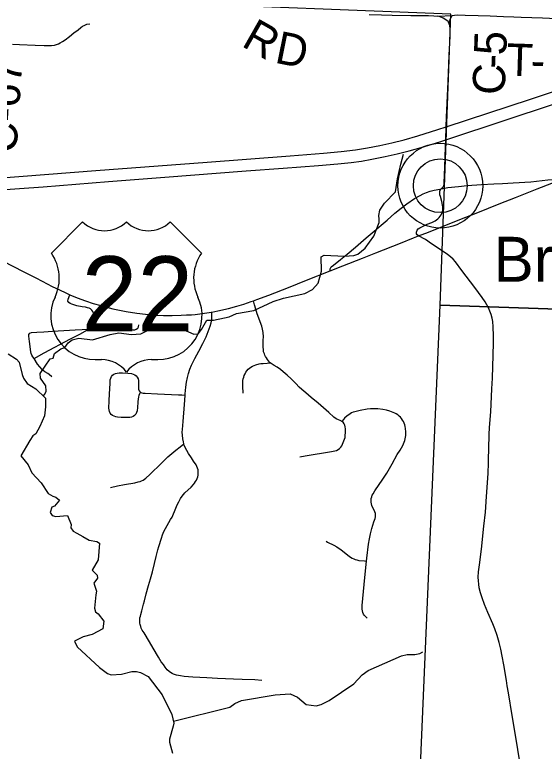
# Model space of a CAD drawing. Extents: x 0 to 34, y 0 to 22.
# Drawn here: x 7.308 to 8.237, y 16.42 to 17.712 of the extents above; entities that cross this region are included whole.
import ezdxf

# ---------------------------------------------------------------- set-up
doc = ezdxf.new("R2010")
doc.units = 0
for name, color, linetype in [('GM_X_County_Road', 7, 'Continuous'), ('GM_X_County_Road_Text', 7, 'Continuous'), ('GM_X_Interstate_Route', 7, 'Continuous'), ('GM_X_Minor_River', 7, 'Continuous'), ('GM_X_Section', 7, 'Continuous'), ('GM_X_Township_Road', 7, 'Continuous'), ('GM_X_Township_Road_Text', 7, 'Continuous'), ('GM_X_Unincorporated', 7, 'Continuous'), ('GM_X_Unincorporated_Location', 7, 'Continuous'), ('GM_X_Unincorporated_Text', 7, 'Continuous'), ('GM_X_US_Location', 7, 'Continuous'), ('GM_X_US_Route', 7, 'Continuous'), ('GM_X_US_Shield', 7, 'Continuous')]:
    doc.layers.add(name, color=color, linetype=linetype)

msp = doc.modelspace()

# ---------------------------------------------------------------- linework, layer by layer
at = {"layer": 'GM_X_County_Road'}
for points in [[(7.9301, 17.7128), (7.9518, 17.7123), (7.9704, 17.7119), (8.0029, 17.7113), (8.0194, 17.711), (8.0344, 17.7108), (8.0433, 17.7107), (8.0499, 17.7101)], [(8.0707, 17.6967), (8.0692, 17.6994), (8.0685, 17.7005), (8.0646, 17.7037), (8.0602, 17.7065), (8.0547, 17.709), (8.0499, 17.7101)], [(8.0562, 17.4067), (8.0602, 17.4101), (8.0613, 17.4124), (8.0615, 17.4152), (8.0616, 17.4213), (8.0621, 17.4275), (8.0623, 17.4338), (8.0627, 17.4429), (8.0632, 17.4646), (8.0644, 17.493), (8.0653, 17.5156), (8.066, 17.5328), (8.0677, 17.5699), (8.0688, 17.5948), (8.0701, 17.6258), (8.0707, 17.6412), (8.0719, 17.6629), (8.0723, 17.6747), (8.0723, 17.681), (8.0722, 17.6876), (8.0718, 17.6935), (8.0707, 17.6967)], [(8.0166, 17.3242), (8.0143, 17.3263), (8.0133, 17.3279), (8.013, 17.3294), (8.013, 17.3308), (8.0137, 17.3326), (8.0145, 17.3343), (8.0163, 17.3366), (8.0187, 17.3385), (8.0222, 17.3402), (8.0259, 17.342), (8.0321, 17.3447), (8.0402, 17.348), (8.0456, 17.3508), (8.0482, 17.3524), (8.0506, 17.3543), (8.0528, 17.3563), (8.0547, 17.3586), (8.0562, 17.3611), (8.0575, 17.3638), (8.0586, 17.3666), (8.0593, 17.3695), (8.0596, 17.3724), (8.0594, 17.3754), (8.059, 17.3784), (8.0577, 17.3844), (8.055, 17.3933), (8.0543, 17.3964), (8.0539, 17.3996), (8.0539, 17.4029), (8.0555, 17.4059), (8.0562, 17.4067)], [(8.196, 16.3904), (8.1856, 16.4548), (8.1809, 16.4823), (8.1744, 16.5221), (8.1724, 16.5344), (8.1709, 16.5436), (8.1661, 16.5711), (8.1635, 16.5864), (8.1609, 16.5986), (8.158, 16.6106), (8.1545, 16.6226), (8.1505, 16.6344), (8.147, 16.6431), (8.1383, 16.663), (8.1323, 16.6773), (8.1281, 16.6889), (8.1254, 16.6977), (8.1232, 16.7067), (8.1223, 16.7128), (8.1217, 16.7189), (8.1216, 16.725), (8.1221, 16.7343), (8.1234, 16.7466), (8.1271, 16.7743), (8.1315, 16.8144), (8.134, 16.8391), (8.1362, 16.867), (8.1388, 16.9072), (8.1395, 16.9258), (8.1403, 16.9568), (8.1406, 16.9692), (8.1408, 16.9753), (8.1415, 16.9877), (8.1433, 17.0155), (8.1456, 17.0558), (8.1463, 17.0744), (8.1478, 17.1147), (8.1485, 17.1365), (8.1485, 17.1489), (8.1477, 17.1645), (8.1468, 17.1738), (8.1458, 17.18), (8.1442, 17.1861), (8.1421, 17.192), (8.1396, 17.1978), (8.1366, 17.2033), (8.1334, 17.2086), (8.1281, 17.2163), (8.1152, 17.2339), (8.0929, 17.2637), (8.0815, 17.2786), (8.0774, 17.2832), (8.0728, 17.2875), (8.0678, 17.2914), (8.0602, 17.2967), (8.0394, 17.3102), (8.0287, 17.3176), (8.0166, 17.3242)]]:
    msp.add_lwpolyline(points, dxfattribs=at)
at = {"layer": 'GM_X_Interstate_Route'}
for points in [[(7.2772, 17.4256), (7.4507, 17.4388), (7.6458, 17.4538), (7.7914, 17.465), (7.8502, 17.4696), (7.8812, 17.4725), (7.9059, 17.4755), (7.9274, 17.4788), (7.9488, 17.4827), (7.9701, 17.4873), (7.9912, 17.4927), (8.0152, 17.4996), (8.0507, 17.5108), (8.0653, 17.5156), (8.213, 17.5644), (8.2553, 17.5781), (8.2721, 17.5836), (8.3164, 17.5982), (8.39, 17.6229), (8.4432, 17.6401), (8.711, 17.7284)], [(7.2745, 17.4042), (7.3581, 17.4105), (7.4727, 17.4194), (7.5717, 17.4272), (7.7142, 17.4382), (7.7792, 17.4432), (7.8412, 17.4478), (7.8752, 17.4508), (7.8986, 17.4531), (7.9165, 17.4556), (7.9349, 17.4589), (7.958, 17.4634), (7.9792, 17.4682), (8.0003, 17.4735), (8.0211, 17.4794), (8.0538, 17.4896), (8.0644, 17.493), (8.0858, 17.4999), (8.1512, 17.5213), (8.2691, 17.5606)]]:
    msp.add_lwpolyline(points, dxfattribs=at)
at = {"layer": 'GM_X_Minor_River'}
for points in [[(7.6764, 17.1802), (7.6846, 17.1821), (7.6971, 17.1882), (7.7277, 17.1934), (7.7617, 17.2088), (7.7795, 17.2149), (7.8169, 17.2228), (7.8305, 17.2301), (7.8407, 17.2415), (7.8462, 17.262), (7.846, 17.2874), (7.8509, 17.2905), (7.8866, 17.2888), (7.9032, 17.2897), (7.9104, 17.2924), (7.9228, 17.3027), (7.9382, 17.324), (7.9479, 17.3476), (7.9479, 17.3533), (7.9471, 17.3601), (7.9489, 17.3696), (7.9568, 17.3814), (7.9763, 17.4017), (7.9796, 17.4241), (7.9859, 17.4499), (7.9903, 17.4674)], [(7.358, 17.0431), (7.3612, 17.0464), (7.3631, 17.0518), (7.363, 17.0609), (7.3535, 17.0745), (7.3527, 17.0824), (7.3704, 17.1087), (7.3753, 17.1095), (7.3779, 17.1179), (7.3888, 17.1259), (7.396, 17.1282), (7.402, 17.1366), (7.4088, 17.1416), (7.4205, 17.1447), (7.4444, 17.1418), (7.4757, 17.1511), (7.4908, 17.1538), (7.5132, 17.1513), (7.5294, 17.1525), (7.5362, 17.1556), (7.5588, 17.1671), (7.5675, 17.1686), (7.5997, 17.1616), (7.6225, 17.1515), (7.63, 17.1523), (7.6357, 17.1599), (7.6451, 17.1763), (7.6568, 17.1763), (7.6764, 17.1802)], [(7.2969, 17.1171), (7.3114, 17.108), (7.3159, 17.1024), (7.3213, 17.0811), (7.3236, 17.0743), (7.3301, 17.0649), (7.3449, 17.0558), (7.362, 17.0392), (7.3621, 17.024), (7.3603, 17.0085), (7.3524, 16.9898), (7.3449, 16.9769), (7.34, 16.9734), (7.3348, 16.9651), (7.3186, 16.938), (7.3316, 16.9221), (7.3381, 16.9081), (7.3548, 16.8908), (7.367, 16.8722), (7.375, 16.8673), (7.3803, 16.8658), (7.3867, 16.8602), (7.3781, 16.8499), (7.3732, 16.8483), (7.3702, 16.8385), (7.3736, 16.8335), (7.3801, 16.8317), (7.4005, 16.8337), (7.407, 16.8174), (7.4063, 16.8117), (7.4105, 16.8057), (7.4173, 16.8023), (7.4275, 16.7966), (7.4385, 16.7902), (7.4522, 16.788), (7.4571, 16.7846), (7.4546, 16.7554), (7.4441, 16.7375), (7.4525, 16.7288), (7.4536, 16.7235), (7.4469, 16.7144), (7.4515, 16.7003), (7.4507, 16.6939), (7.4482, 16.6707), (7.4498, 16.6646), (7.4547, 16.6609), (7.4642, 16.648), (7.4628, 16.6343), (7.4443, 16.6248), (7.428, 16.6205), (7.4133, 16.6128), (7.4175, 16.603), (7.4567, 16.5667), (7.4707, 16.5562), (7.4775, 16.5536), (7.4953, 16.5548), (7.5135, 16.5598), (7.5218, 16.5595), (7.5286, 16.558), (7.5422, 16.5509), (7.5666, 16.5187), (7.5838, 16.4843), (7.5873, 16.4691), (7.5862, 16.4634), (7.5795, 16.441), (7.5795, 16.4353), (7.5849, 16.4163)], [(7.5865, 16.4724), (7.6858, 16.497), (7.6941, 16.5035), (7.7062, 16.5085), (7.7652, 16.5188), (7.7913, 16.5201), (7.8046, 16.5148), (7.8195, 16.5017), (7.8373, 16.4991), (7.846, 16.5014), (7.8599, 16.5087), (7.9029, 16.5378), (7.9176, 16.5539), (7.9285, 16.5611), (7.9871, 16.5869), (7.9965, 16.5893), (8.0102, 16.5893), (8.0192, 16.5909), (8.0245, 16.594)]]:
    msp.add_lwpolyline(points, dxfattribs=at)
at = {"layer": 'GM_X_Section'}
for points in [[(7.5782, 18.246), (8.5787, 18.2117), (8.5361, 17.186), (8.0548, 17.2024), (8.0736, 17.7137), (7.5651, 17.7332)], [(8.0548, 17.2024), (8.5361, 17.186), (8.4938, 16.1751), (8.0113, 16.1881)]]:
    msp.add_lwpolyline(points, close=True, dxfattribs=at)
at = {"layer": 'GM_X_Township_Road'}
msp.add_line((8.0499, 17.7101), (8.0762, 17.7113), dxfattribs=at)
for points in [[(8.0707, 17.6967), (8.0711, 17.7001), (8.0715, 17.7019), (8.072, 17.704), (8.0726, 17.7058), (8.0734, 17.7072), (8.0752, 17.7098), (8.0762, 17.7113)], [(8.0762, 17.7113), (8.0799, 17.7118), (8.0848, 17.712), (8.0988, 17.7118), (8.1212, 17.7112), (8.1425, 17.7105), (8.1658, 17.7095), (8.1841, 17.7087), (8.1969, 17.708), (8.2154, 17.7073), (8.234, 17.7067), (8.2463, 17.7063), (8.2658, 17.7057), (8.2864, 17.7047), (8.3106, 17.7036), (8.3324, 17.7021), (8.3538, 17.7008), (8.3699, 17.7001), (8.3856, 17.6998), (8.4067, 17.6991), (8.4217, 17.6989)], [(7.3045, 17.6606), (7.3167, 17.6603), (7.3441, 17.6589), (7.3596, 17.6582), (7.3658, 17.6582), (7.3726, 17.6584), (7.3782, 17.659), (7.3814, 17.6599), (7.3849, 17.6612), (7.3878, 17.6628), (7.3918, 17.6652), (7.3966, 17.6685), (7.4045, 17.6744), (7.4119, 17.6804), (7.4192, 17.6862), (7.4242, 17.6902), (7.4269, 17.6921), (7.4298, 17.6937), (7.4325, 17.6949), (7.4348, 17.6957), (7.4401, 17.6964)], [(8.0562, 17.4067), (8.0682, 17.4089), (8.0866, 17.4112), (8.1023, 17.4127), (8.1271, 17.4142), (8.1488, 17.4153), (8.1643, 17.4161), (8.183, 17.4172), (8.2136, 17.4193), (8.2437, 17.4225), (8.2517, 17.4232), (8.2562, 17.4221), (8.26, 17.4199)], [(7.8617, 17.2629), (7.8618, 17.2661), (7.8622, 17.2678), (7.8628, 17.2689), (7.8634, 17.2697), (7.8673, 17.273), (7.8796, 17.2825), (7.8917, 17.2923), (7.9058, 17.3046), (7.9246, 17.3207), (7.9388, 17.3326), (7.9511, 17.343), (7.9615, 17.352), (7.975, 17.3639), (7.9861, 17.373), (7.996, 17.3803), (8.0099, 17.3898), (8.0195, 17.3954), (8.0248, 17.398), (8.0306, 17.4006), (8.0372, 17.4028), (8.044, 17.4043), (8.0541, 17.4064), (8.0551, 17.4065), (8.0562, 17.4067)], [(7.4423, 17.1623), (7.4446, 17.1732), (7.4461, 17.1792), (7.4466, 17.1822), (7.4468, 17.1853), (7.4464, 17.1884), (7.4454, 17.1913), (7.4437, 17.1939), (7.4413, 17.1959), (7.4386, 17.1973), (7.4356, 17.1982), (7.4326, 17.1989), (7.4265, 17.1999), (7.4173, 17.2014), (7.4083, 17.2042), (7.4054, 17.2053), (7.403, 17.2071), (7.4016, 17.2098), (7.4018, 17.2129), (7.405, 17.221)], [(7.7565, 17.1015), (7.7554, 17.1023), (7.7532, 17.1047), (7.7514, 17.1073), (7.7499, 17.1099), (7.7484, 17.1124), (7.7471, 17.115), (7.7462, 17.1172), (7.7449, 17.1207), (7.7444, 17.124), (7.744, 17.1294), (7.7442, 17.1413), (7.7444, 17.1472), (7.7438, 17.1548), (7.7429, 17.1604), (7.7416, 17.1659), (7.739, 17.1732), (7.7365, 17.1796), (7.7335, 17.1875), (7.7311, 17.1956), (7.7291, 17.2034), (7.7273, 17.2103)], [(7.6072, 17.0449), (7.6074, 17.0469), (7.6085, 17.0586), (7.6096, 17.0675), (7.6113, 17.0758), (7.6129, 17.0828), (7.6155, 17.0903), (7.6186, 17.0973), (7.6242, 17.1089), (7.6312, 17.1216), (7.6382, 17.1356), (7.6439, 17.1468), (7.6477, 17.1562), (7.6511, 17.1659), (7.653, 17.1717), (7.6537, 17.1746), (7.6539, 17.177), (7.6542, 17.1806), (7.654, 17.1861), (7.6539, 17.1904)], [(7.342, 17.109), (7.3399, 17.1122), (7.3384, 17.1149), (7.3372, 17.1177), (7.3363, 17.1207), (7.3338, 17.139), (7.3328, 17.1482), (7.3328, 17.1513), (7.3345, 17.1536), (7.3375, 17.1545), (7.3467, 17.1554), (7.359, 17.156), (7.3743, 17.157), (7.4144, 17.1591), (7.4386, 17.1606)], [(7.342, 17.109), (7.3595, 17.119), (7.406, 17.1434), (7.4224, 17.1519), (7.436, 17.1591), (7.4386, 17.1606)], [(7.4386, 17.1606), (7.4415, 17.162), (7.4423, 17.1623)], [(7.4423, 17.1623), (7.4444, 17.1629), (7.4475, 17.163), (7.4845, 17.1611), (7.5061, 17.1597), (7.5153, 17.1594), (7.5186, 17.1596), (7.5215, 17.1603), (7.5239, 17.162), (7.5252, 17.1648), (7.5259, 17.1678)], [(7.3734, 17.0769), (7.3686, 17.081), (7.3661, 17.0827), (7.3608, 17.0858), (7.3583, 17.0877), (7.356, 17.0897), (7.3519, 17.0943), (7.3482, 17.0992), (7.342, 17.109)], [(7.7088, 17.0481), (7.7086, 17.0607), (7.7084, 17.067), (7.7086, 17.0701), (7.7091, 17.0732), (7.71, 17.0762), (7.711, 17.0792), (7.7123, 17.0821), (7.7137, 17.0849), (7.7155, 17.0875), (7.7175, 17.09), (7.7198, 17.0921), (7.7224, 17.0939), (7.7252, 17.0954), (7.7281, 17.0966), (7.7311, 17.0977), (7.7371, 17.0994), (7.7402, 17.1), (7.7442, 17.1005), (7.751, 17.101), (7.7565, 17.1015)], [(7.8823, 16.9985), (7.8818, 16.9989), (7.879, 17.0003), (7.8733, 17.0027), (7.8706, 17.0042), (7.8682, 17.006), (7.8591, 17.0145), (7.8403, 17.0307), (7.8284, 17.0407), (7.8188, 17.0485), (7.8118, 17.0546), (7.8075, 17.0587), (7.8013, 17.0651), (7.793, 17.0734), (7.7864, 17.0797), (7.7794, 17.0854), (7.7742, 17.0896), (7.7687, 17.0935), (7.7632, 17.0968), (7.7584, 17.1001), (7.7565, 17.1015)], [(7.5275, 17.0481), (7.526, 17.0441), (7.5254, 17.0416), (7.5252, 17.0402), (7.5249, 17.0385), (7.5244, 17.0325), (7.5238, 17.0231), (7.5229, 17.0169), (7.522, 17.014), (7.5206, 17.0112), (7.5185, 17.009), (7.516, 17.0072), (7.5132, 17.006), (7.5102, 17.0054), (7.5071, 17.0052), (7.4947, 17.0054), (7.4886, 17.006), (7.4856, 17.0066), (7.4826, 17.0075), (7.4798, 17.0089), (7.4774, 17.0107), (7.4755, 17.0131), (7.4742, 17.0159), (7.4736, 17.019), (7.4735, 17.0221), (7.474, 17.0345), (7.4743, 17.0468), (7.4754, 17.0653), (7.4758, 17.0715), (7.4766, 17.0745), (7.4779, 17.0773), (7.4798, 17.0797), (7.4823, 17.0815), (7.4851, 17.0827), (7.4881, 17.0833), (7.4912, 17.0836), (7.4974, 17.0837), (7.5067, 17.0832), (7.5128, 17.0824), (7.5158, 17.0816), (7.5187, 17.0804), (7.5212, 17.0787), (7.5232, 17.0764), (7.5245, 17.0735), (7.5252, 17.0705), (7.5255, 17.0643), (7.5254, 17.055), (7.5257, 17.0533), (7.5262, 17.052), (7.5281, 17.0498), (7.5309, 17.0487), (7.5333, 17.0484), (7.5371, 17.0483), (7.5586, 17.047), (7.5831, 17.0458), (7.5954, 17.0453), (7.6016, 17.0451), (7.6072, 17.0449)], [(7.6048, 16.9591), (7.604, 16.9625), (7.603, 16.9677), (7.6023, 16.9743), (7.6021, 16.9797), (7.6024, 16.9845), (7.603, 16.9915), (7.6035, 16.9984), (7.6041, 17.006), (7.6055, 17.0207), (7.6064, 17.0361), (7.6072, 17.0449)], [(7.9255, 16.7532), (7.9261, 16.7586), (7.9291, 16.7831), (7.9306, 16.7923), (7.9324, 16.8014), (7.9346, 16.8105), (7.9364, 16.8164), (7.9385, 16.8222), (7.9404, 16.828), (7.941, 16.8309), (7.9413, 16.8339), (7.941, 16.8369), (7.9403, 16.8398), (7.939, 16.8426), (7.9361, 16.8481), (7.9349, 16.851), (7.9339, 16.8539), (7.9334, 16.8569), (7.9333, 16.86), (7.9337, 16.863), (7.9345, 16.866), (7.9356, 16.8689), (7.937, 16.8716), (7.9402, 16.8769), (7.9543, 16.8973), (7.9609, 16.9079), (7.9702, 16.9241), (7.9794, 16.9403), (7.9842, 16.9483), (7.9889, 16.9563), (7.9915, 16.9619), (7.9925, 16.9648), (7.9933, 16.9678), (7.9942, 16.974), (7.9943, 16.9802), (7.9938, 16.9864), (7.9932, 16.9894), (7.9925, 16.9925), (7.9915, 16.9954), (7.9903, 16.9983), (7.9888, 17.001), (7.9871, 17.0035), (7.985, 17.0059), (7.9827, 17.008), (7.9803, 17.0099), (7.9777, 17.0116), (7.975, 17.0131), (7.9722, 17.0145), (7.9664, 17.0167), (7.9604, 17.0182), (7.9543, 17.0194), (7.945, 17.0204), (7.9388, 17.0207), (7.9326, 17.0205), (7.9264, 17.0199), (7.9142, 17.0177), (7.9051, 17.0156), (7.9021, 17.0147), (7.8993, 17.0134), (7.8966, 17.0119), (7.8941, 17.0102), (7.8916, 17.0082), (7.887, 17.0041), (7.885, 17.0017), (7.8823, 16.9985)], [(7.8087, 16.9366), (7.8179, 16.9381), (7.8639, 16.9455), (7.87, 16.9467), (7.8729, 16.9477), (7.8756, 16.9492), (7.8781, 16.9511), (7.8802, 16.9534), (7.8819, 16.9559), (7.8834, 16.9587), (7.8859, 16.9644), (7.8869, 16.9673), (7.8877, 16.9703), (7.8882, 16.9733), (7.8887, 16.9795), (7.8886, 16.9857), (7.8882, 16.9888), (7.8874, 16.9918), (7.8861, 16.9946), (7.8842, 16.997), (7.8823, 16.9985)], [(7.4759, 16.8827), (7.4882, 16.8854), (7.5005, 16.8878), (7.519, 16.891), (7.525, 16.8923), (7.528, 16.8932), (7.5308, 16.8943), (7.5335, 16.8956), (7.536, 16.8973), (7.5384, 16.8992), (7.5453, 16.9056), (7.5654, 16.9253), (7.5767, 16.9362), (7.5838, 16.9424), (7.5911, 16.9483), (7.5984, 16.9541), (7.6048, 16.9591)], [(7.7415, 16.5438), (7.7292, 16.5448), (7.7075, 16.5457), (7.692, 16.5463), (7.6641, 16.5475), (7.6455, 16.5483), (7.6207, 16.5496), (7.6053, 16.5508), (7.5991, 16.5517), (7.5918, 16.5531), (7.587, 16.555), (7.5841, 16.5562), (7.5816, 16.5577), (7.5791, 16.5597), (7.5758, 16.5626), (7.5721, 16.567), (7.5689, 16.5717), (7.5653, 16.5767), (7.5603, 16.5846), (7.5512, 16.6008), (7.5449, 16.6114), (7.5351, 16.6272), (7.5318, 16.6323), (7.5302, 16.6354), (7.5294, 16.6383), (7.5283, 16.6419), (7.5279, 16.6446), (7.5279, 16.6479), (7.5279, 16.6508), (7.5279, 16.6535), (7.5287, 16.6566), (7.5295, 16.6599), (7.5309, 16.6659), (7.5341, 16.6778), (7.5357, 16.6837), (7.539, 16.6957), (7.5431, 16.7105), (7.5466, 16.7224), (7.5496, 16.7344), (7.5533, 16.7494), (7.5561, 16.7615), (7.5593, 16.7733), (7.5611, 16.779), (7.5655, 16.7937), (7.5674, 16.7996), (7.5698, 16.8052), (7.5725, 16.8107), (7.5785, 16.8214), (7.5816, 16.8262), (7.5841, 16.8302), (7.587, 16.8366), (7.5884, 16.8406), (7.5897, 16.8434), (7.5932, 16.8519), (7.5959, 16.8574), (7.5988, 16.8632), (7.602, 16.8675), (7.6067, 16.8731), (7.6178, 16.8834), (7.6219, 16.888), (7.6238, 16.8904), (7.6255, 16.893), (7.6271, 16.8957), (7.6284, 16.8985), (7.6294, 16.9015), (7.63, 16.9045), (7.6302, 16.9076), (7.6302, 16.9107), (7.6298, 16.9137), (7.629, 16.9167), (7.6278, 16.9196), (7.6264, 16.9224), (7.6218, 16.929), (7.6181, 16.9346), (7.6133, 16.9421), (7.61, 16.9473), (7.6068, 16.9538), (7.6056, 16.9566), (7.6048, 16.9591)], [(7.8544, 16.7882), (7.857, 16.7868), (7.8679, 16.7812), (7.8732, 16.7782), (7.8808, 16.7732), (7.8832, 16.7713), (7.8927, 16.7636), (7.8976, 16.76), (7.9002, 16.7585), (7.9029, 16.7571), (7.9057, 16.7561), (7.9087, 16.7553), (7.9117, 16.7547), (7.9219, 16.7536), (7.9255, 16.7532)], [(7.9264, 16.6534), (7.924, 16.6554), (7.9219, 16.6577), (7.9202, 16.6603), (7.9189, 16.663), (7.9181, 16.666), (7.9177, 16.6691), (7.9176, 16.6722), (7.9178, 16.6753), (7.9202, 16.7), (7.9225, 16.7247), (7.9255, 16.7532)]]:
    msp.add_lwpolyline(points, dxfattribs=at)
at = {"layer": 'GM_X_Unincorporated'}
for radius in [0.0744, 0.0472]:
    msp.add_circle((8.0549, 17.4123), radius, dxfattribs=at)
at = {"layer": 'GM_X_Unincorporated_Location'}
msp.add_line((8.0549, 17.4123), (8.0549, 17.4123), dxfattribs=at)
at = {"layer": 'GM_X_US_Route'}
for points in [[(8.0166, 17.3242), (8.034, 17.331), (8.0889, 17.3527), (8.1206, 17.3655), (8.1581, 17.3805), (8.1871, 17.3916), (8.2073, 17.3998), (8.2246, 17.4066), (8.2507, 17.4165), (8.26, 17.4199)], [(7.1802, 17.3223), (7.1878, 17.3204), (7.2014, 17.3165), (7.2162, 17.3119), (7.2308, 17.3067), (7.2452, 17.3008), (7.2592, 17.2943), (7.3035, 17.2717), (7.3255, 17.2603), (7.3449, 17.2503), (7.356, 17.2448), (7.3739, 17.2355), (7.3864, 17.2293), (7.3977, 17.2241), (7.405, 17.221)], [(7.8617, 17.2629), (7.8837, 17.2717), (7.9184, 17.2853), (7.9415, 17.2944), (7.9849, 17.3115), (8.008, 17.3208), (8.0166, 17.3242)], [(7.7273, 17.2103), (7.7328, 17.2123), (7.7538, 17.2202), (7.7885, 17.2339), (7.8203, 17.2464), (7.8617, 17.2629)], [(7.405, 17.221), (7.4178, 17.2156), (7.4322, 17.21), (7.4458, 17.2056), (7.459, 17.2018), (7.48, 17.1964), (7.492, 17.1937), (7.5039, 17.1914), (7.5223, 17.1884), (7.5378, 17.1867), (7.5533, 17.1853), (7.5689, 17.1845), (7.5844, 17.1844), (7.6, 17.185), (7.6093, 17.1855), (7.6186, 17.1859), (7.6248, 17.1864), (7.6372, 17.1878), (7.6495, 17.1895), (7.6526, 17.1901), (7.6539, 17.1904)], [(7.6539, 17.1904), (7.6648, 17.1925), (7.683, 17.1967), (7.6981, 17.2006), (7.71, 17.2042), (7.7232, 17.2088), (7.7273, 17.2103)]]:
    msp.add_lwpolyline(points, dxfattribs=at)
at = {"layer": 'GM_X_US_Shield'}
for p, q in [((7.4273, 17.3489), (7.3724, 17.2939)), ((7.636, 17.2939), (7.5811, 17.3489)), ((7.4493, 17.1072), (7.4602, 17.1072)), ((7.5481, 17.1072), (7.5591, 17.1072))]:
    msp.add_line(p, q, dxfattribs=at)
for centre, radius, start, end in [((7.4657, 17.3881), 0.0549, 225.573, 314.427), ((7.5426, 17.3881), 0.0549, 225.573, 314.427), ((7.3094, 17.2498), 0.0769, 334.5471, 35.0009), ((7.699, 17.2498), 0.0769, 144.9991, 205.4529), ((7.4484, 17.1841), 0.0769, 154.8319, 270.6383), ((7.56, 17.1841), 0.0769, 269.3617, 25.1681), ((7.4602, 17.0522), 0.0549, 36.8699, 90), ((7.5481, 17.0522), 0.0549, 90, 143.1301)]:
    msp.add_arc(centre, radius, start, end, dxfattribs=at)

# ---------------------------------------------------------------- texts
at = {"layer": 'GM_X_County_Road_Text'}
for s, height, rotation, p in [('R', 0.0568, 330.4454, (7.7041, 17.6584)), ('D', 0.0568, 348.5923, (7.7627, 17.6286)), ('5', 0.0568, 88.1063, (8.1706, 17.6407)), ('-', 0.0568, 87.6316, (8.1696, 17.6171)), ('C-67', 0.05682, 86.2797, (7.311, 17.4683)), ('C', 0.0568, 87.6075, (8.1677, 17.5708))]:
    msp.add_text(s, height=height, rotation=rotation, dxfattribs=at).set_placement(p)
at = {"layer": 'GM_X_Township_Road_Text'}
for s, p in [('T', (8.1704, 17.6055)), ('-', (8.2128, 17.6042))]:
    msp.add_text(s, height=0.0568, rotation=358.2414, dxfattribs=at).set_placement(p)
at = {"layer": 'GM_X_Unincorporated_Text'}
msp.add_text('Bridgeville', height=0.078977, rotation=0, dxfattribs=at).set_placement((8.1484, 17.2436))
at = {"layer": 'GM_X_US_Location'}
for s in ['0', '/']:
    msp.add_text(s, height=0.000189, dxfattribs=at).set_placement((7.5041, 17.2215))
msp.add_text('22', height=0.000189, rotation=0, dxfattribs=at).set_placement((7.465, 17.1823))
at = {"layer": 'GM_X_US_Shield'}
msp.add_text('22', height=0.13184, dxfattribs=at).set_placement((7.4254, 17.1566))

doc.saveas('drawing.dxf')
